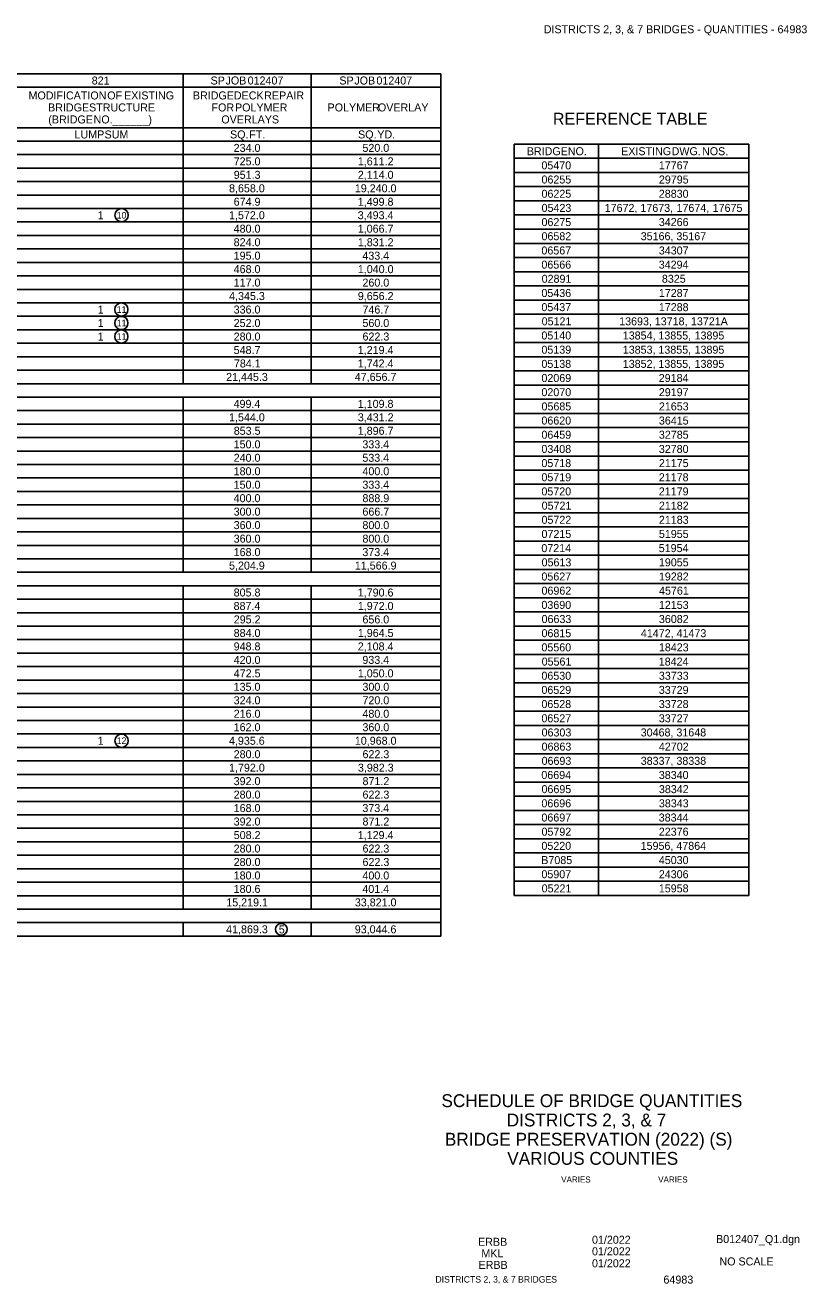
# Model space of a CAD drawing. Extents: x 16 to 1228740, y 11 to 152440.
# Drawn here: x 17.42 to 18.436, y 10.769 to 12.405 of the extents above; entities that cross this region are included whole.
import ezdxf

# ---------------------------------------------------------------- set-up
doc = ezdxf.new("R2010")
doc.units = 0
for name, color, linetype in [('B_Copy In', 7, 'Continuous'), ('B_Text', 7, 'Continuous'), ('Default', 7, 'Continuous')]:
    doc.layers.add(name, color=color, linetype=linetype)

msp = doc.modelspace()

# ---------------------------------------------------------------- linework, layer by layer
at = {"layer": 'B_Text'}
msp.add_line((18.0555, 12.2505), (18.0555, 12.2505), dxfattribs=at)
for centre, radius in [((17.5457, 12.1581), 0.0086), ((17.5454, 12.0355), 0.0086), ((17.5454, 12.018), 0.0086), ((17.5454, 12.0004), 0.0086), ((17.5457, 11.475), 0.0086), ((17.7532, 11.2299), 0.00762)]:
    msp.add_circle(centre, radius, dxfattribs=at)
at = {"layer": 'Default'}
for p, q in [((15.8634, 12.342), (17.9605, 12.342)), ((17.6259, 11.9391), (17.6259, 12.342)), ((17.7918, 11.9391), (17.7918, 12.342)), ((17.9605, 11.2211), (17.9605, 12.342)), ((16.6976, 12.3244), (17.9605, 12.3244)), ((16.6976, 12.2719), (17.9605, 12.2719)), ((15.8634, 12.2544), (17.9605, 12.2544)), ((17.6259, 11.9567), (17.6259, 12.2544)), ((18.0555, 12.2505), (18.3605, 12.2505)), ((18.0555, 11.2739), (18.0555, 12.2505)), ((18.1652, 11.2739), (18.1652, 12.2505)), ((18.3605, 11.2739), (18.3605, 12.2505)), ((15.9436, 12.2369), (17.9605, 12.2369)), ((18.0555, 12.2321), (18.3605, 12.2321)), ((15.9436, 12.2194), (17.9605, 12.2194)), ((18.0555, 12.2137), (18.3605, 12.2137)), ((15.9436, 12.2019), (17.9605, 12.2019)), ((18.0555, 12.1953), (18.3605, 12.1953)), ((15.9436, 12.1843), (17.9605, 12.1843)), ((18.0555, 12.1768), (18.3605, 12.1768)), ((15.9436, 12.1668), (17.9605, 12.1668)), ((18.0555, 12.1584), (18.3605, 12.1584)), ((15.9436, 12.1493), (17.9605, 12.1493)), ((18.0555, 12.14), (18.3605, 12.14)), ((15.9436, 12.1318), (17.9605, 12.1318)), ((15.9436, 12.1143), (17.9605, 12.1143)), ((18.0555, 12.1215), (18.3605, 12.1215)), ((15.9436, 12.0968), (17.9605, 12.0968)), ((18.0555, 12.1031), (18.3605, 12.1031)), ((15.9436, 12.0793), (17.9605, 12.0793)), ((18.0555, 12.0847), (18.3605, 12.0847)), ((15.9436, 12.0617), (17.9605, 12.0617)), ((18.0555, 12.0663), (18.3605, 12.0663)), ((15.9436, 12.0442), (17.9605, 12.0442)), ((18.0555, 12.0478), (18.3605, 12.0478)), ((15.9436, 12.0267), (17.9605, 12.0267)), ((18.0555, 12.0294), (18.3605, 12.0294)), ((15.9436, 12.0092), (17.9605, 12.0092)), ((18.0555, 12.011), (18.3605, 12.011)), ((18.0555, 11.9925), (18.3605, 11.9925)), ((15.9436, 11.9917), (17.9605, 11.9917)), ((15.9436, 11.9742), (17.9605, 11.9742)), ((18.0555, 11.9741), (18.3605, 11.9741)), ((15.9436, 11.9567), (17.9605, 11.9567)), ((18.0555, 11.9557), (18.3605, 11.9557)), ((15.8634, 11.9391), (17.9605, 11.9391)), ((18.0555, 11.9373), (18.3605, 11.9373)), ((15.8634, 11.9216), (17.9605, 11.9216)), ((17.6259, 11.694), (17.6259, 11.9216)), ((17.7918, 11.694), (17.7918, 11.9216)), ((18.0555, 11.9188), (18.3605, 11.9188)), ((15.9436, 11.9041), (17.9605, 11.9041)), ((18.0555, 11.9004), (18.3605, 11.9004)), ((15.9436, 11.8866), (17.9605, 11.8866)), ((18.0555, 11.882), (18.3605, 11.882)), ((15.9436, 11.8691), (17.9605, 11.8691)), ((18.0555, 11.8636), (18.3605, 11.8636)), ((15.9436, 11.8516), (17.9605, 11.8516)), ((18.0555, 11.8451), (18.3605, 11.8451)), ((15.9436, 11.8341), (17.9605, 11.8341)), ((15.9436, 11.8166), (17.9605, 11.8166)), ((18.0555, 11.8267), (18.3605, 11.8267)), ((15.9436, 11.799), (17.9605, 11.799)), ((18.0555, 11.8083), (18.3605, 11.8083)), ((15.9436, 11.7815), (17.9605, 11.7815)), ((18.0555, 11.7898), (18.3605, 11.7898)), ((15.9436, 11.764), (17.9605, 11.764)), ((18.0555, 11.7714), (18.3605, 11.7714)), ((18.0555, 11.753), (18.3605, 11.753)), ((15.9436, 11.7465), (17.9605, 11.7465)), ((18.0555, 11.7346), (18.3605, 11.7346)), ((15.9436, 11.729), (17.9605, 11.729)), ((18.0555, 11.7161), (18.3605, 11.7161)), ((15.9436, 11.7115), (17.9605, 11.7115)), ((18.0555, 11.6977), (18.3605, 11.6977)), ((15.8634, 11.694), (17.9605, 11.694)), ((15.8634, 11.6764), (17.9605, 11.6764)), ((17.6259, 11.2561), (17.6259, 11.6764)), ((17.7918, 11.2561), (17.7918, 11.6764)), ((18.0555, 11.6793), (18.3605, 11.6793)), ((15.9436, 11.6589), (17.9605, 11.6589)), ((18.0555, 11.6609), (18.3605, 11.6609)), ((15.9436, 11.6414), (17.9605, 11.6414)), ((17.0756, 11.6414), (17.9605, 11.6414)), ((18.0555, 11.6424), (18.3605, 11.6424)), ((15.9436, 11.6239), (17.9605, 11.6239)), ((18.0555, 11.624), (18.3605, 11.624)), ((15.9436, 11.6064), (17.9605, 11.6064)), ((18.0555, 11.6056), (18.3605, 11.6056)), ((15.9436, 11.5889), (17.9605, 11.5889)), ((18.0555, 11.5871), (18.3605, 11.5871)), ((15.9436, 11.5714), (17.9605, 11.5714)), ((18.0555, 11.5687), (18.3605, 11.5687)), ((15.9436, 11.5539), (17.9605, 11.5539)), ((15.9436, 11.5363), (17.9605, 11.5363)), ((18.0555, 11.5503), (18.3605, 11.5503)), ((15.9436, 11.5188), (17.9605, 11.5188)), ((18.0555, 11.5319), (18.3605, 11.5319)), ((18.0555, 11.5134), (18.3605, 11.5134)), ((15.9436, 11.5013), (17.9605, 11.5013)), ((18.0555, 11.495), (18.3605, 11.495)), ((15.9436, 11.4838), (17.9605, 11.4838)), ((18.0555, 11.4766), (18.3605, 11.4766)), ((15.9436, 11.4663), (17.9605, 11.4663)), ((18.0555, 11.4582), (18.3605, 11.4582)), ((15.9436, 11.4488), (17.9605, 11.4488)), ((18.0555, 11.4397), (18.3605, 11.4397)), ((15.9436, 11.4313), (17.9605, 11.4313)), ((18.0555, 11.4213), (18.3605, 11.4213)), ((15.9436, 11.4137), (17.9605, 11.4137)), ((15.9436, 11.3962), (17.9605, 11.3962)), ((18.0555, 11.4029), (18.3605, 11.4029)), ((15.9436, 11.3787), (17.9605, 11.3787)), ((18.0555, 11.3844), (18.3605, 11.3844)), ((15.9436, 11.3612), (17.9605, 11.3612)), ((18.0555, 11.366), (18.3605, 11.366)), ((15.9436, 11.3437), (17.9605, 11.3437)), ((18.0555, 11.3476), (18.3605, 11.3476)), ((15.9436, 11.3262), (17.9605, 11.3262)), ((18.0555, 11.3292), (18.3605, 11.3292)), ((15.9436, 11.3087), (17.9605, 11.3087)), ((18.0555, 11.3107), (18.3605, 11.3107)), ((15.9436, 11.2911), (17.9605, 11.2911)), ((18.0555, 11.2923), (18.3605, 11.2923)), ((15.9436, 11.2736), (17.9605, 11.2736)), ((18.0555, 11.2739), (18.3605, 11.2739)), ((15.8634, 11.2561), (17.9605, 11.2561)), ((15.8634, 11.2386), (17.9605, 11.2386)), ((17.6259, 11.2211), (17.6259, 11.2386)), ((17.7918, 11.2211), (17.7918, 11.2386)), ((15.8634, 11.2211), (17.9605, 11.2211))]:
    msp.add_line(p, q, dxfattribs=at)

# ---------------------------------------------------------------- texts
at = {"layer": 'B_Copy In'}
for s, height, p in [('DISTRICTS 2, 3, & 7 BRIDGES - QUANTITIES - 64983', 0.0104, (18.0941, 12.3946)), ('SCHEDULE OF BRIDGE QUANTITIES', 0.0167, (17.9612, 10.9988)), ('DISTRICTS 2, 3, & 7', 0.0167, (18.046, 10.9737)), ('BRIDGE PRESERVATION (2022) (S)', 0.0167, (17.9657, 10.9487)), ('VARIOUS COUNTIES', 0.0167, (18.0467, 10.9238)), ('VARIES', 0.0078, (18.1168, 10.9008)), ('VARIES', 0.0078, (18.2428, 10.9008)), ('01/2022', 0.0104, (18.1568, 10.8212)), ('B012407_Q1.dgn', 0.0104, (18.318, 10.8221)), ('ERBB', 0.0104, (18.0088, 10.8185)), ('01/2022', 0.0104, (18.1568, 10.8062)), ('ERBB', 0.0104, (18.0094, 10.7885)), ('MKL', 0.0104, (18.0131, 10.8035)), ('01/2022', 0.0104, (18.1568, 10.7906)), ('NO SCALE', 0.0104, (18.3224, 10.793)), ('DISTRICTS 2, 3, & 7 BRIDGES', 0.0084, (17.9534, 10.7707)), ('64983', 0.01042, (18.2496, 10.7694))]:
    msp.add_text(s, height=height, dxfattribs=at).set_placement(p)
at = {"layer": 'B_Text'}
for s, height, p in [('REFERENCE TABLE', 0.015625, (18.106, 12.2756)), ('10', 0.0085, (17.5393, 12.1538)), ('11', 0.0085, (17.5393, 12.0312)), ('11', 0.0085, (17.5393, 12.0137)), ('11', 0.0085, (17.5393, 11.9962)), ('12', 0.0085, (17.5393, 11.4708)), ('5', 0.0104, (17.7499, 11.2246))]:
    msp.add_text(s, height=height, dxfattribs=at).set_placement(p)
at = {"layer": 'Default'}
for s, height, p in [('821', 0.0104, (17.5069, 12.328)), ('SP', 0.0104, (17.6613, 12.328)), (' JOB', 0.0104, (17.6769, 12.328)), (' 012407', 0.0104, (17.7056, 12.328)), ('SP', 0.0104, (17.8286, 12.328)), (' JOB', 0.0104, (17.8442, 12.328)), (' 012407', 0.0104, (17.8729, 12.328)), ('MODIFICATION', 0.010399, (17.4248, 12.3086)), ('BRIDGE', 0.0104, (17.4502, 12.293)), (' STRUCTURE', 0.0104, (17.4996, 12.293)), (' OF', 0.0104, (17.5232, 12.3086)), (' EXISTING', 0.0104, (17.5451, 12.3086)), ('BRIDGE', 0.0104, (17.6383, 12.3086)), ('FOR', 0.0104, (17.6625, 12.293)), (' DECK', 0.0104, (17.6877, 12.3086)), (' POLYMER', 0.0104, (17.6892, 12.293)), (' REPAIR', 0.0104, (17.7271, 12.3086)), ('POLYMER', 0.0104, (17.8133, 12.293)), (' OVERLAY', 0.0104, (17.8748, 12.293)), ('(BRIDGE', 0.0104, (17.4505, 12.2774)), (' NO.______)', 0.010399, (17.5055, 12.2774)), ('OVERLAYS', 0.0104, (17.6753, 12.2774)), ('LUMP', 0.0104, (17.4846, 12.2579)), (' SUM', 0.0104, (17.5197, 12.2579)), ('SQ.', 0.0104, (17.6866, 12.2579)), (' FT.', 0.0104, (17.7077, 12.2579)), ('SQ.', 0.0104, (17.8529, 12.2579)), (' YD.', 0.0104, (17.874, 12.2579)), ('234.0', 0.0104, (17.6913, 12.2404)), ('520.0', 0.0104, (17.8586, 12.2404)), ('BRIDGE', 0.01039, (18.0721, 12.2361)), (' NO.', 0.01039, (18.1215, 12.2361)), ('EXISTING', 0.01039, (18.1947, 12.2361)), (' DWG.', 0.01039, (18.2564, 12.2361)), (' NOS.', 0.01039, (18.2959, 12.2361)), ('725.0', 0.0104, (17.6913, 12.2229)), ('1,611.2', 0.0104, (17.8526, 12.2229)), ('05470', 0.01039, (18.0911, 12.2177)), ('17767', 0.01039, (18.2436, 12.2177)), ('951.3', 0.0104, (17.6914, 12.2054)), ('2,114.0', 0.0104, (17.8526, 12.2054)), ('06255', 0.01039, (18.0912, 12.1993)), ('29795', 0.01039, (18.2437, 12.1993)), ('8,658.0', 0.0104, (17.6853, 12.1879)), ('19,240.0', 0.0104, (17.8487, 12.1879)), ('06225', 0.01039, (18.0912, 12.1808)), ('28830', 0.01039, (18.2436, 12.1808)), ('674.9', 0.0104, (17.6913, 12.1704)), ('1,499.8', 0.0104, (17.8525, 12.1704)), ('05423', 0.01039, (18.0913, 12.1624)), ('17672,', 0.01039, (18.1733, 12.1624)), (' 17673,', 0.01039, (18.2158, 12.1624)), (' 17674,', 0.01039, (18.2627, 12.1624)), (' 17675', 0.01039, (18.3097, 12.1624)), ('1', 0.0104, (17.5147, 12.1529)), ('1,572.0', 0.0104, (17.6853, 12.1529)), ('3,493.4', 0.0104, (17.8525, 12.1529)), ('480.0', 0.0104, (17.6913, 12.1354)), ('1,066.7', 0.0104, (17.8525, 12.1354)), ('06275', 0.01039, (18.0912, 12.144)), ('34266', 0.01039, (18.2436, 12.144)), ('824.0', 0.0104, (17.6913, 12.1178)), ('1,831.2', 0.0104, (17.8526, 12.1178)), ('06582', 0.01039, (18.0912, 12.1256)), ('35166,', 0.01039, (18.2201, 12.1256)), (' 35167', 0.01039, (18.2626, 12.1256)), ('195.0', 0.0104, (17.6913, 12.1003)), ('433.4', 0.0104, (17.8585, 12.1003)), ('06567', 0.01039, (18.0911, 12.1071)), ('34307', 0.01039, (18.2436, 12.1071)), ('468.0', 0.0104, (17.6913, 12.0828)), ('1,040.0', 0.0104, (17.8526, 12.0828)), ('06566', 0.01039, (18.0911, 12.0887)), ('34294', 0.01039, (18.2435, 12.0887)), ('117.0', 0.0104, (17.6913, 12.0653)), ('260.0', 0.0104, (17.8586, 12.0653)), ('02891', 0.01039, (18.0914, 12.0703)), ('8325', 0.01039, (18.2476, 12.0703)), ('4,345.3', 0.0104, (17.6854, 12.0478)), ('9,656.2', 0.0104, (17.8526, 12.0478)), ('05436', 0.01039, (18.0911, 12.0518)), ('17287', 0.01039, (18.2436, 12.0518)), ('05437', 0.01039, (18.0911, 12.0334)), ('17288', 0.01039, (18.2436, 12.0334)), ('1', 0.0104, (17.5147, 12.0303)), ('336.0', 0.0104, (17.6913, 12.0303)), ('746.7', 0.0104, (17.8586, 12.0303)), ('05121', 0.01039, (18.0914, 12.015)), ('13693,', 0.01039, (18.1921, 12.015)), (' 13718,', 0.01039, (18.2345, 12.015)), (' 13721A', 0.01039, (18.2815, 12.015)), ('1', 0.0104, (17.5147, 12.0128)), ('252.0', 0.0104, (17.6913, 12.0128)), ('560.0', 0.0104, (17.8586, 12.0128)), ('1', 0.0104, (17.5147, 11.9952)), ('280.0', 0.0104, (17.6913, 11.9952)), ('622.3', 0.0104, (17.8587, 11.9952)), ('05140', 0.01039, (18.0911, 11.9966)), ('13854,', 0.01039, (18.1968, 11.9966)), (' 13855,', 0.01039, (18.2392, 11.9966)), (' 13895', 0.01039, (18.2862, 11.9966)), ('548.7', 0.0104, (17.6913, 11.9777)), ('1,219.4', 0.0104, (17.8525, 11.9777)), ('05139', 0.01039, (18.0911, 11.9781)), ('13853,', 0.01039, (18.1968, 11.9781)), (' 13855,', 0.01039, (18.2392, 11.9781)), (' 13895', 0.01039, (18.2862, 11.9781)), ('784.1', 0.0104, (17.6916, 11.9602)), ('1,742.4', 0.0104, (17.8525, 11.9602)), ('05138', 0.01039, (18.0911, 11.9597)), ('13852,', 0.01039, (18.1968, 11.9597)), (' 13855,', 0.01039, (18.2392, 11.9597)), (' 13895', 0.01039, (18.2862, 11.9597)), ('21,445.3', 0.0104, (17.6815, 11.9427)), ('47,656.7', 0.0104, (17.8486, 11.9427)), ('02069', 0.01039, (18.0911, 11.9413)), ('29184', 0.01039, (18.2435, 11.9413)), ('02070', 0.01039, (18.0911, 11.9229)), ('29197', 0.01039, (18.2436, 11.9229)), ('499.4', 0.0104, (17.6912, 11.9077)), ('1,109.8', 0.0104, (17.8525, 11.9077)), ('05685', 0.01039, (18.0912, 11.9044)), ('21653', 0.01039, (18.2437, 11.9044)), ('1,544.0', 0.0104, (17.6853, 11.8902)), ('3,431.2', 0.0104, (17.8526, 11.8902)), ('06620', 0.01039, (18.0911, 11.886)), ('36415', 0.01039, (18.2437, 11.886)), ('853.5', 0.0104, (17.6914, 11.8727)), ('1,896.7', 0.0104, (17.8525, 11.8727)), ('06459', 0.01039, (18.0911, 11.8676)), ('32785', 0.01039, (18.2437, 11.8676)), ('150.0', 0.0104, (17.6913, 11.8551)), ('333.4', 0.0104, (17.8585, 11.8551)), ('240.0', 0.0104, (17.6913, 11.8376)), ('533.4', 0.0104, (17.8585, 11.8376)), ('03408', 0.01039, (18.0911, 11.8491)), ('32780', 0.01039, (18.2436, 11.8491)), ('180.0', 0.0104, (17.6913, 11.8201)), ('400.0', 0.0104, (17.8586, 11.8201)), ('05718', 0.01039, (18.0911, 11.8307)), ('21175', 0.01039, (18.2437, 11.8307)), ('150.0', 0.0104, (17.6913, 11.8026)), ('333.4', 0.0104, (17.8585, 11.8026)), ('05719', 0.01039, (18.0911, 11.8123)), ('21178', 0.01039, (18.2436, 11.8123)), ('05720', 0.01039, (18.0911, 11.7939)), ('21179', 0.01039, (18.2436, 11.7939)), ('400.0', 0.0104, (17.6913, 11.7851)), ('888.9', 0.0104, (17.8586, 11.7851)), ('05721', 0.01039, (18.0914, 11.7754)), ('21182', 0.01039, (18.2437, 11.7754)), ('300.0', 0.0104, (17.6913, 11.7676)), ('666.7', 0.0104, (17.8586, 11.7676)), ('05722', 0.01039, (18.0912, 11.757)), ('21183', 0.01039, (18.2437, 11.757)), ('360.0', 0.0104, (17.6913, 11.7501)), ('800.0', 0.0104, (17.8586, 11.7501)), ('07215', 0.01039, (18.0912, 11.7386)), ('51955', 0.01039, (18.2437, 11.7386)), ('360.0', 0.0104, (17.6913, 11.7325)), ('800.0', 0.0104, (17.8586, 11.7325)), ('07214', 0.01039, (18.091, 11.7202)), ('51954', 0.01039, (18.2435, 11.7202)), ('168.0', 0.0104, (17.6913, 11.715)), ('373.4', 0.0104, (17.8585, 11.715)), ('5,204.9', 0.0104, (17.6853, 11.6975)), ('11,566.9', 0.0104, (17.8487, 11.6975)), ('05613', 0.01039, (18.0913, 11.7017)), ('19055', 0.01039, (18.2437, 11.7017)), ('05627', 0.01039, (18.0911, 11.6833)), ('19282', 0.01039, (18.2437, 11.6833)), ('805.8', 0.0104, (17.6913, 11.6625)), ('1,790.6', 0.0104, (17.8525, 11.6625)), ('06962', 0.01039, (18.0912, 11.6649)), ('45761', 0.01039, (18.2439, 11.6649)), ('887.4', 0.0104, (17.6912, 11.645)), ('1,972.0', 0.0104, (17.8526, 11.645)), ('03690', 0.01039, (18.0911, 11.6464)), ('12153', 0.01039, (18.2437, 11.6464)), ('295.2', 0.0104, (17.6914, 11.6275)), ('656.0', 0.0104, (17.8586, 11.6275)), ('06633', 0.01039, (18.0913, 11.628)), ('36082', 0.01039, (18.2437, 11.628)), ('884.0', 0.0104, (17.6913, 11.6099)), ('1,964.5', 0.0104, (17.8526, 11.6099)), ('06815', 0.01039, (18.0912, 11.6096)), ('41472,', 0.01039, (18.2203, 11.6096)), (' 41473', 0.01039, (18.2628, 11.6096)), ('948.8', 0.0104, (17.6913, 11.5924)), ('2,108.4', 0.0104, (17.8525, 11.5924)), ('05560', 0.01039, (18.0911, 11.5912)), ('18423', 0.01039, (18.2437, 11.5912)), ('420.0', 0.0104, (17.6913, 11.5749)), ('933.4', 0.0104, (17.8585, 11.5749)), ('05561', 0.01039, (18.0914, 11.5727)), ('18424', 0.01039, (18.2435, 11.5727)), ('472.5', 0.0104, (17.6914, 11.5574)), ('1,050.0', 0.0104, (17.8526, 11.5574)), ('135.0', 0.0104, (17.6913, 11.5399)), ('300.0', 0.0104, (17.8586, 11.5399)), ('06530', 0.01039, (18.0911, 11.5543)), ('33733', 0.01039, (18.2437, 11.5543)), ('06529', 0.01039, (18.0911, 11.5359)), ('33729', 0.01039, (18.2436, 11.5359)), ('324.0', 0.0104, (17.6913, 11.5224)), ('720.0', 0.0104, (17.8586, 11.5224)), ('06528', 0.01039, (18.0911, 11.5175)), ('33728', 0.01039, (18.2436, 11.5175)), ('216.0', 0.0104, (17.6913, 11.5049)), ('480.0', 0.0104, (17.8586, 11.5049)), ('06527', 0.01039, (18.0911, 11.499)), ('33727', 0.01039, (18.2436, 11.499)), ('162.0', 0.0104, (17.6913, 11.4874)), ('360.0', 0.0104, (17.8586, 11.4874)), ('06303', 0.01039, (18.0913, 11.4806)), ('30468,', 0.01039, (18.2201, 11.4806)), (' 31648', 0.01039, (18.2626, 11.4806)), ('1', 0.0104, (17.5147, 11.4698)), ('4,935.6', 0.0104, (17.6852, 11.4698)), ('10,968.0', 0.0104, (17.8487, 11.4698)), ('06863', 0.01039, (18.0913, 11.4622)), ('42702', 0.01039, (18.2437, 11.4622)), ('280.0', 0.0104, (17.6913, 11.4523)), ('622.3', 0.0104, (17.8587, 11.4523)), ('06693', 0.01039, (18.0913, 11.4437)), ('38337,', 0.01039, (18.2201, 11.4437)), (' 38338', 0.01039, (18.2626, 11.4437)), ('1,792.0', 0.0104, (17.6853, 11.4348)), ('3,982.3', 0.0104, (17.8527, 11.4348)), ('392.0', 0.0104, (17.6913, 11.4173)), ('871.2', 0.0104, (17.8587, 11.4173)), ('06694', 0.01039, (18.091, 11.4253)), ('38340', 0.01039, (18.2436, 11.4253)), ('280.0', 0.0104, (17.6913, 11.3998)), ('622.3', 0.0104, (17.8587, 11.3998)), ('06695', 0.01039, (18.0912, 11.4069)), ('38342', 0.01039, (18.2437, 11.4069)), ('168.0', 0.0104, (17.6913, 11.3823)), ('373.4', 0.0104, (17.8585, 11.3823)), ('06696', 0.01039, (18.0911, 11.3885)), ('38343', 0.01039, (18.2437, 11.3885)), ('392.0', 0.0104, (17.6913, 11.3648)), ('871.2', 0.0104, (17.8587, 11.3648)), ('06697', 0.01039, (18.0911, 11.37)), ('38344', 0.01039, (18.2435, 11.37)), ('508.2', 0.0104, (17.6914, 11.3472)), ('1,129.4', 0.0104, (17.8525, 11.3472)), ('05792', 0.01039, (18.0912, 11.3516)), ('22376', 0.01039, (18.2436, 11.3516)), ('280.0', 0.0104, (17.6913, 11.3297)), ('622.3', 0.0104, (17.8587, 11.3297)), ('05220', 0.01039, (18.0911, 11.3332)), ('15956,', 0.01039, (18.22, 11.3332)), (' 47864', 0.01039, (18.2625, 11.3332)), ('280.0', 0.0104, (17.6913, 11.3122)), ('622.3', 0.0104, (17.8587, 11.3122)), ('B7085', 0.01039, (18.0909, 11.3147)), ('45030', 0.01039, (18.2436, 11.3147)), ('180.0', 0.0104, (17.6913, 11.2947)), ('400.0', 0.0104, (17.8586, 11.2947)), ('05907', 0.01039, (18.0911, 11.2963)), ('24306', 0.01039, (18.2436, 11.2963)), ('180.6', 0.0104, (17.6913, 11.2772)), ('401.4', 0.0104, (17.8585, 11.2772)), ('05221', 0.01039, (18.0914, 11.2779)), ('15958', 0.01039, (18.2436, 11.2779)), ('15,219.1', 0.0104, (17.6817, 11.2597)), ('33,821.0', 0.0104, (17.8487, 11.2597)), ('41,869.3', 0.0104, (17.6815, 11.2247)), ('93,044.6', 0.0104, (17.8486, 11.2247))]:
    msp.add_text(s, height=height, dxfattribs=at).set_placement(p)

doc.saveas('drawing.dxf')
